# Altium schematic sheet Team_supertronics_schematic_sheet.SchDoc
size A; SheetNumber: 1; SheetTotal: 1
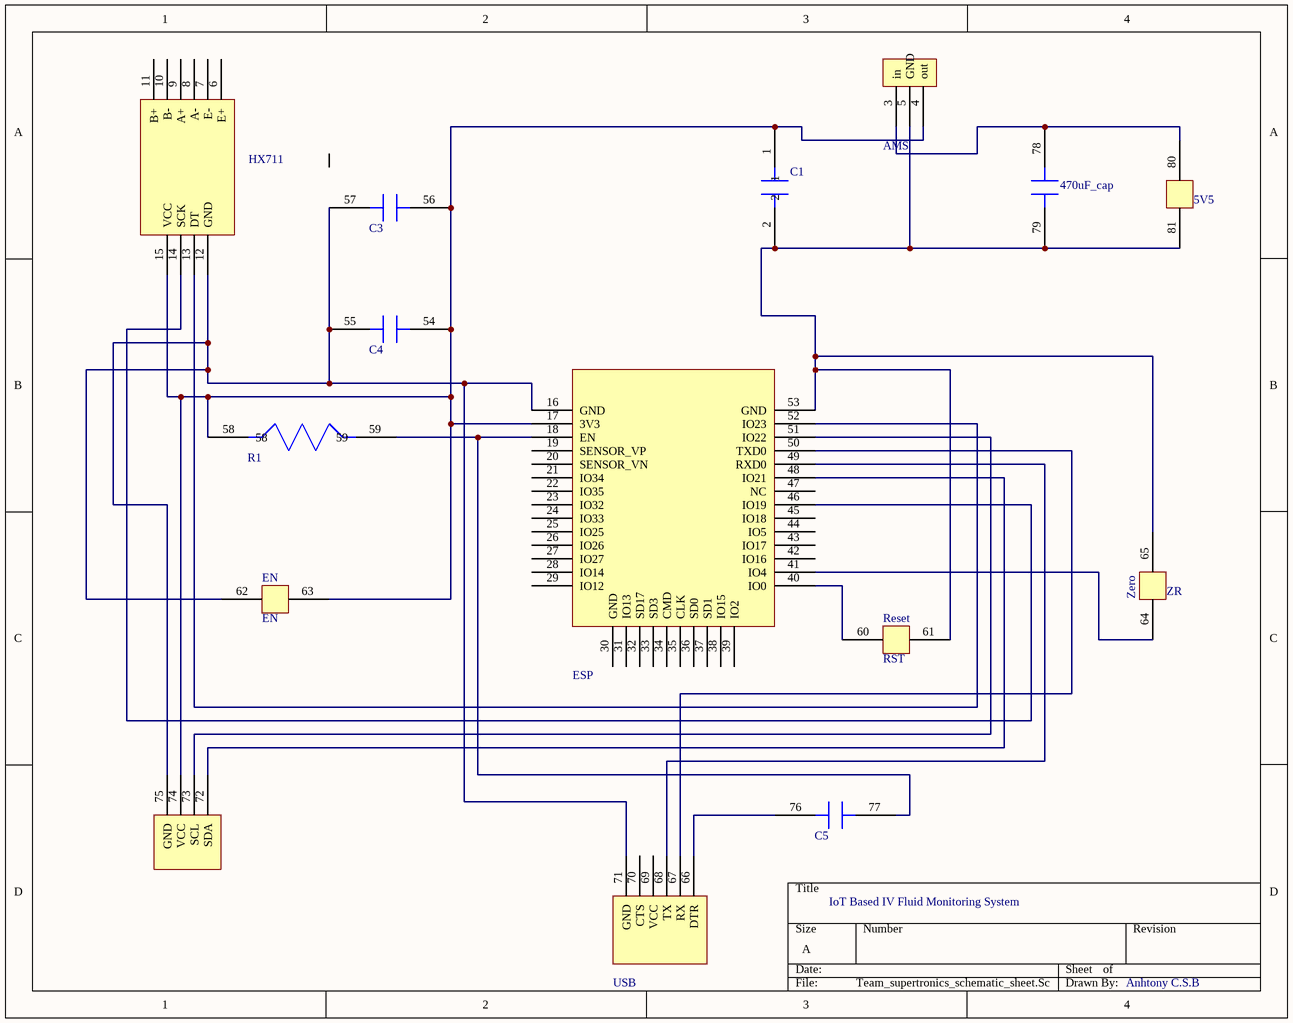
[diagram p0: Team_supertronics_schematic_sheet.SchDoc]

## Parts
5V5  5V  [5V5]  (value not drawn)
AMS  AMS1117-3.3S  [AMS1117-3.3s]  (value not drawn)
C1  Capacitor_16ZLJ470MTA8X11.5  [Cap_470_16z]  (value not drawn)
C2  470uF_cap  [470uF_Capacitor]
C3  Capacitor_10uF  [10uF_Capacitor]  (value not drawn)
C4  Capacitor_0.1uF  [Cap_0.1uF]  (value not drawn)
C5  2_Capacitor_0.1uF  [0.1uF_Capacitor]  (value not drawn)
DS  Digital_screen  [Digital_screen]  (value not drawn)
EN  EN_push_button  [EN_push_button]  (value not drawn)
ESP  ESP32_WROOM_32D  [ESP32_WROOM32D]  (value not drawn)
HX  HX711  [HX711]
R1  Resistor_10k  [10K_ohm_resistor]  (value not drawn)
RST  Reset_push_button  [Reset_push_button]  (value not drawn)
USB  USB_port  [USB_port]  (value not drawn)
ZR  zero_push_button  [Zero_push_button]  (value not drawn)

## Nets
Net5V5_80: 5V5.80 AMS.3(in) C2.78
Net5V5_81: 5V5.81 AMS.5(GND) C1.2 C2.79 ESP.53(GND) RST.61 ZR.65
NetAMS_4: AMS.4(out) C1.1 C3.56 C4.54 DS.74(VCC) EN.63 ESP.17(3V3) HX.15(VCC) R1.58
NetC3_ 57: C3.57 C4.55 DS.75(GND) EN.62 ESP.16(GND) HX.12(GND) USB.71(GND)
NetC5_76: C5.76 USB.66(DTR)
NetC5_77: C5.77 ESP.18(EN) R1.59
NetDS_72: DS.72(SDA) ESP.48(IO21)
NetDS_73: DS.73(SCL) ESP.51(IO22)
NetESP_40: ESP.40(IO0) RST.60
NetESP_41: ESP.41(IO4) ZR.64
NetESP_46: ESP.46(IO19) HX.14(SCK)
NetESP_49: ESP.49(RXD0) USB.68(TX)
NetESP_50: ESP.50(TXD0) USB.67(RX)
NetESP_52: ESP.52(IO23) HX.13(DT)

Not connected (* = marked no-connect by the designer): ESP 19(SENSOR_VP) 20(SENSOR_VN) 21(IO34) 22(IO35) 23(IO32) 24(IO33) 25(IO25) 26(IO26) 27(IO27) 28(IO14) 29(IO12) 30(GND) 31(IO13) 32(SD17) 33(SD3) 34(CMD) 35(CLK) 36(SD0) 37(SD1) 38(IO15) 39(IO2) 42(IO16) 43(IO17) 44(IO5) 45(IO18) 47(NC); HX 6(E+) 7(E-) 8(A-) 9(A+) 10(B-) 11(B+); USB 69(VCC) 70(CTS)

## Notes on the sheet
- IoT Based IV Fluid Monitoring System
- Anhtony C.S.B

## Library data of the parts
AMS = AMS1117-3.3S: Linear Voltage Regulator IC Positive Fixed 1 Output 1A SOT-89
C1 = Capacitor_16ZLJ470MTA8X11.5: 470 µF 16 V Aluminum Electrolytic Capacitors Radial, Can 9000 Hrs @ 105°C
C2 = 470uF_cap: 470 µF 16 V Aluminum Electrolytic Capacitors Radial, Can 9000 Hrs @ 105°C
C3 = Capacitor_10uF: 10uF
C4 = Capacitor_0.1uF: 0.1uF
EN = EN_push_button: EN
R1 = Resistor_10k: 10kOhm
RST = Reset_push_button: Reset
ZR = zero_push_button: Zero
